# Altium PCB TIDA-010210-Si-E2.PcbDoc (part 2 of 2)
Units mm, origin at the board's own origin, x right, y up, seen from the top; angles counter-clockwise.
Board outline 75 x 60 mm, 2 copper layers (Top Layer, Bottom Layer), stack 1.565 mm thick; 77 components, 33 nets, 164 pads, 32 vias.
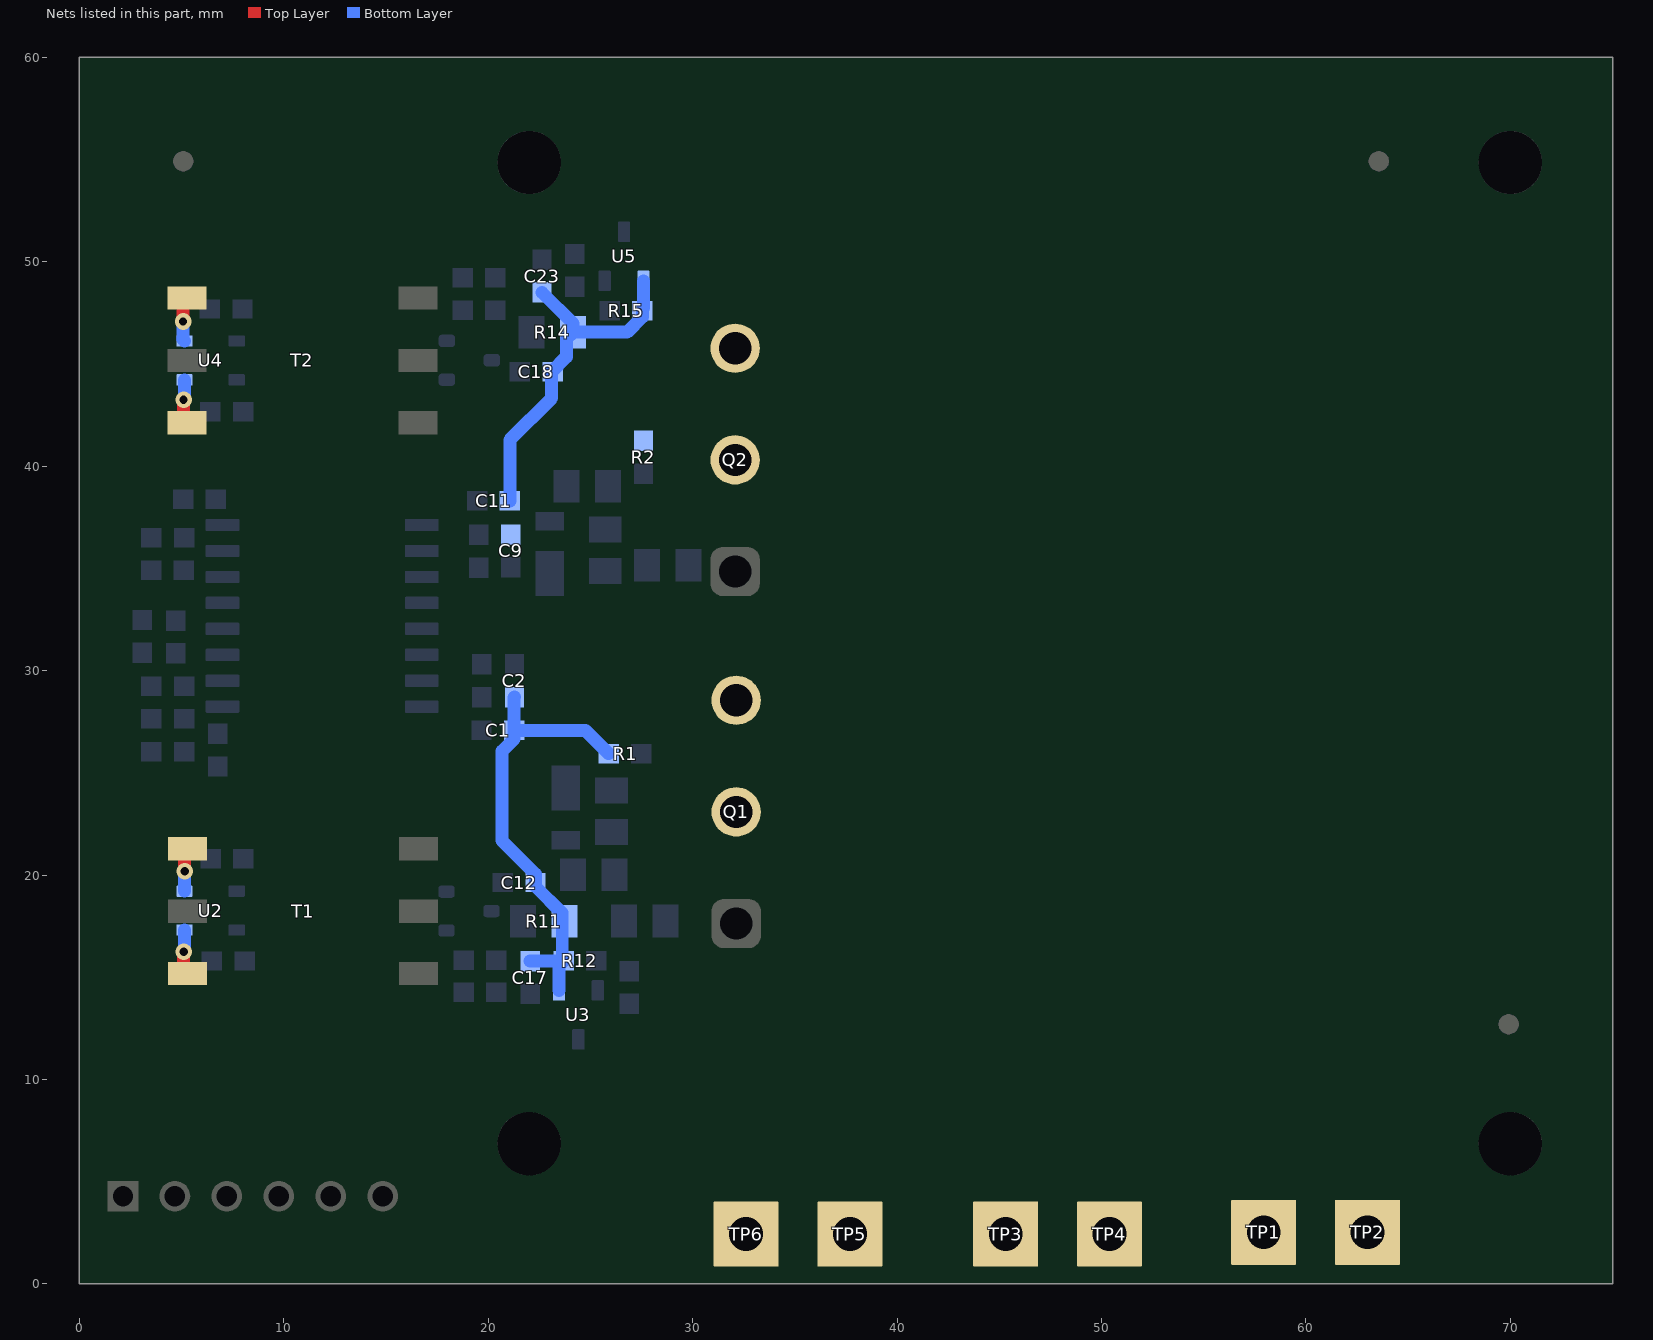
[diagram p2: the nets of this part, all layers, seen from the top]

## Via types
v1: diameter 0.813, hole 0.406, Top Layer to Bottom Layer, tented both sides, 31 vias
v2: diameter 0.813, hole 0.406, Top Layer to Bottom Layer, 1 vias

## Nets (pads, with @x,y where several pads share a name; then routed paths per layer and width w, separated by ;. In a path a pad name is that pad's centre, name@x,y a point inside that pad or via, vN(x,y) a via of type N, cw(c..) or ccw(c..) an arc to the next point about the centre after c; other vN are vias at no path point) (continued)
NetT1_1: T1.1 U2.3 | length 2.1
  Top Layer w0.63: v1(5.149,20.191) 5.149,21.149 T1.1@5.286,21.285
  Bottom Layer w0.635: U2.3@5.144,19.211 5.144,20.186 v1(5.149,20.191)
NetT1_3: T1.3 U2.1 | length 2.2
  Top Layer w0.63: v1(5.099,16.254) 5.099,15.372 T1.3@5.286,15.185
  Bottom Layer w0.635: v1(5.099,16.254) 5.144,16.3 U2.1@5.144,17.311
NetT2_1: T2.1 U4.3 | length 2.2
  Top Layer w0.63: v1(5.072,47.081) 5.072,48.039 T2.1@5.259,48.226
  Bottom Layer w0.635: v1(5.072,47.081) 5.072,46.197 U4.3@5.144,46.126
NetT2_3: T2.3 U4.1 | length 2.2
  Top Layer w0.63: v1(5.098,43.258) 5.098,42.288 T2.3@5.259,42.126
  Bottom Layer w0.635: v1(5.098,43.258) 5.144,43.304 U4.1@5.144,44.226
SW: C1.2 C2.2 C12.2 C17.1 Q1.3 Q2.2 R1.1 R11.1 R12.2 TP1.1 TP2.1 U3.1 | length 22.6
  Bottom Layer w0.635: C2.2@21.284,28.704 21.272,28.692 C1.2@21.272,27.076 ; C17.1@22.047,15.786 R12.2@23.673,15.786 ; U3.1@23.459,14.357 R12.2@23.459,15.471 ; R12.2@23.459,15.573 R12.2@23.673,15.786 ; R1.1@25.895,25.933 24.752,27.076 C1.2@21.272,27.076 ; C1.2@21.272,27.076 21.272,26.657 20.676,26.06 20.676,21.68 22.314,20.042 C12.2@22.314,19.634 22.314,19.444 23.622,18.136 23.622,17.735 23.622,15.862 R12.2@23.686,15.799 R12.2@23.673,15.786
SW+: Q1.2 TP3.1 TP4.1
SW-: C9.2 C11.2 C18.2 C23.1 Q2.3 R2.1 R14.1 R15.2 TP5.1 TP6.1 U5.1 | length 17.6
  Bottom Layer w0.635: C11.2@21.059,38.305 21.059,41.29 23.101,43.332 23.101,44.628 23.825,45.352 23.825,46.228 R14.1@24.155,46.558 ; C23.1@22.631,48.501 24.155,46.977 R14.1@24.155,46.558 ; U5.1@27.595,49.067 27.595,47.74 27.545,47.691 27.545,47.306 26.797,46.558 R14.1@24.155,46.558
pads on no net: "Heat Sink1.1" "Heat Sink1.2" "Heat Sink1.3" "Heat Sink1.4" FID4.1 FID5.1 FID6.1 FID7.1 FID8.1 FID9.1 J1.5 U1.7 U1.12 U1.13

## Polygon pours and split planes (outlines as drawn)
SW- on Top Layer "TOP_LAYER_SW-_P119" (solid, remove dead copper, pour order 119): 50.952,43.926 52.781,42.099 52.781,17.45 41.173,5.842 41.173,2.611 39.223,0.66 29.017,0.66 28.473,1.204 28.473,8.585 35.966,16.078 35.966,42.088 33.96,44.094 31.166,44.094 30.582,44.679 30.582,46.507 31.496,47.422 47.457,47.422
NetD1_1 on Top Layer "TOP_LAYER_NETD1_1_P095" (solid, remove dead copper, pour order 95): 19.619,30.063 22.454,27.229 22.454,23.216 22.123,22.885 20.345,22.885 17.094,26.137 17.094,29.758 17.399,30.063
GND on Top Layer "TOP_LAYER_GND_P067" (solid, remove dead copper, pour order 67): 0.765,38.89 0.765,47.679 2.184,49.098 7.468,49.098 7.496,49.07 7.496,38.489 7.496,12.596 15.151,4.94 15.151,3.632 12.256,0.737 1.626,0.737 0.765,1.597 0.765,25.199
NetD2_1 on Top Layer "TOP_LAYER_NETD2_1_P043" (solid, remove dead copper, pour order 43): 22.276,34.306 22.673,33.909 24.502,33.909 24.816,34.218 24.816,35.792 23.905,36.703 17.399,36.703 17.013,36.317 17.013,35.412 17.155,35.27 18.582,35.27 19.028,34.824 19.028,34.475 19.197,34.306
SW on Bottom Layer "BOTTOM_LAYER_SW_P121" (solid, remove dead copper, pour order 121): 32.925,27.127 52.019,27.127 55.575,23.571 55.575,1.575 56.464,0.686 67.793,0.686 68.631,1.524 68.631,33.68 60.427,41.885 31.394,41.885 30.632,41.123 30.632,39.472 31.369,38.735 33.571,38.735 35.966,36.339 35.966,33.299 33.376,30.709 23.368,30.709 21.996,29.337 20.813,29.337 20.559,29.083 20.559,26.685 20.86,26.384 26.384,26.384 27.11,27.11 32.907,27.11
SW+ on Bottom Layer "BOTTOM_LAYER_SW+_P117" (solid, remove dead copper, pour order 117): 43.424,11.898 33.706,21.615 31.369,21.615 30.709,22.276 30.709,24.105 31.115,24.511 48.692,24.511 52.781,20.422 52.781,1.295 52.121,0.635 43.993,0.635 43.424,1.204
GND on Bottom Layer "BOTTOM_LAYER_GND_P111" (solid, remove dead copper, pour order 111): 7.188,40.963 8.414,42.189 8.414,48.151 7.468,49.098 2.184,49.098 0.765,47.679 0.765,1.597 1.626,0.737 12.256,0.737 15.151,3.632 15.151,4.94 8.441,11.651 8.441,24.63 7.188,25.883
+12Va on Bottom Layer "BOTTOM_LAYER_+12VA_P109" (solid, remove dead copper, pour order 109): 19.355,19.341 19.761,18.935 19.761,13.894 19.888,13.767 20.973,13.767 21.125,13.919 21.125,16.61 21.234,16.719 22.206,16.719 22.377,16.891 22.377,18.52 22.127,18.771 21.641,18.771 21.234,19.177 21.234,20.085 19.793,21.526 19.494,21.526 19.355,21.387
+12Vb on Bottom Layer "BOTTOM_LAYER_+12VB_P107" (solid, remove dead copper, pour order 107): 19.787,44.45 20.091,44.145 22.047,44.145 22.2,44.298 22.2,45.364 22.377,45.542 22.759,45.542 22.962,45.745 22.962,47.193 22.581,47.574 21.92,47.574 21.615,47.879 21.615,49.352 21.26,49.708 19.837,49.708 19.837,49.706 19.685,49.553 19.685,48.285 19.787,48.184
NetD1_2 on Bottom Layer "BOTTOM_LAYER_NETD1_2_P105" (solid, remove dead copper, pour order 105): 23.038,22.377 22.606,21.946 22.606,21.108 23.292,20.422 23.292,19.45 23.743,18.999 24.759,18.999 24.962,19.202 24.962,20.784 24.663,21.082 24.663,22.2 24.486,22.377
NetL1_1 on Bottom Layer "BOTTOM_LAYER_NETL1_1_P103" (solid, remove dead copper, pour order 103): 27.127,16.739 25.639,16.739 25.359,17.018 25.359,20.889 25.014,21.234 25.014,22.638 25.287,22.911 26.645,22.911 26.822,22.733 26.822,21.016 27.381,20.457 27.381,16.993
G1H_P on Bottom Layer "BOTTOM_LAYER_G1H_P_P101" (solid, remove dead copper, pour order 101): 33.004,18.821 33.35,18.475 33.35,16.767 32.995,16.411 28.185,16.411 27.807,16.789 27.807,18.586 28.042,18.821
+12Va on Bottom Layer "BOTTOM_LAYER_+12VA_P099" (solid, remove dead copper, pour order 99): 15.981,28.423 16.106,28.547 18.673,28.547 19.329,29.202 20.15,29.202 20.226,29.126 20.226,26.627 19.964,26.365 17.551,26.365 15.981,27.935
-5Va on Bottom Layer "BOTTOM_LAYER_-5VA_P097" (solid, remove dead copper, pour order 97): 15.981,30.963 15.981,30.967 16.307,31.293 21.71,31.293 21.975,31.028 21.971,31.024 21.971,29.972 21.733,29.734 19.395,29.734 19.395,29.969 18.884,30.48 16.096,30.48 15.981,30.594
NetD1_1 on Bottom Layer "BOTTOM_LAYER_NETD1_1_P089" (solid, remove dead copper, pour order 89): 21.336,25.146 21.336,23.203 21.654,22.885 24.587,22.885 25.095,23.393 26.721,23.393 26.822,23.495 26.822,24.892 26.619,25.095 25.159,25.095 24.651,25.603 21.793,25.603
G1L_P on Bottom Layer "BOTTOM_LAYER_G1L_P_P087" (solid, remove dead copper, pour order 87): 29.616,36.398 29.108,35.89 29.108,33.68 29.515,33.274 32.893,33.274 33.528,33.909 33.528,35.719 32.849,36.398
NetL2_1 on Bottom Layer "BOTTOM_LAYER_NETL2_1_P085" (solid, remove dead copper, pour order 85): 25.221,39.827 25.221,39.824 24.994,39.596 24.994,37.744 24.79,37.541 24.79,36.246 24.917,36.119 26.467,36.119 26.975,35.611 26.975,34.315 27.203,34.087 28.372,34.087 28.626,34.341 28.626,36.792 26.721,38.697 26.721,39.649 26.543,39.827
NetD2_2 on Bottom Layer "BOTTOM_LAYER_NETD2_2_P083" (solid, remove dead copper, pour order 83): 22.327,36.881 22.327,39.116 23.037,39.827 24.46,39.827 24.613,39.675 24.613,37.916 24.384,37.688 24.384,37.008 24.181,36.805 22.402,36.805
+12Vb on Bottom Layer "BOTTOM_LAYER_+12VB_P081" (solid, remove dead copper, pour order 81): 15.981,34.773 15.981,34.404 15.981,34.387 16.307,34.061 21.234,34.061 21.615,34.442 21.615,35.509 21.488,35.636 19.501,35.636 18.739,34.874 16.083,34.874
-5Vb on Bottom Layer "BOTTOM_LAYER_-5VB_P079" (solid, remove dead copper, pour order 79): 15.981,37.313 15.981,38.003 17.196,39.218 19.558,39.218 19.939,38.837 19.939,36.346 19.763,36.17 19.119,36.17 18.484,36.805 16.121,36.805 15.981,36.944
SW- on Bottom Layer "BOTTOM_LAYER_SW-_P077" (solid, remove dead copper, pour order 77): 32.791,44.094 33.61,44.913 33.61,46.578 32.791,47.422 28.829,47.422 27.28,45.872 25.728,45.872 23.661,43.805 21.644,43.805 20.372,42.534 20.377,36.417 20.701,36.093 21.565,36.096 21.906,36.437 21.906,39.331 22.809,40.234 26.619,40.234 30.48,44.094
NetD1_1 on Bottom Layer "BOTTOM_LAYER_NETD1_1_P047" (solid, remove dead copper, pour order 47): 18.569,30.063 18.926,29.706 18.926,29.167 18.776,29.016 15.991,29.017 15.864,29.144 15.864,29.972 15.955,30.063
NetD2_1 on Bottom Layer "BOTTOM_LAYER_NETD2_1_P045" (solid, remove dead copper, pour order 45): 17.721,36.375 18.342,36.375 18.621,36.096 18.621,35.605 18.446,35.43 15.946,35.43 15.889,35.487 15.889,36.215 16.049,36.375
NetD2_1 on Bottom Layer "BOTTOM_LAYER_NETD2_1_P039" (solid, remove dead copper, pour order 39): 22.415,36.218 22.243,36.043 22.243,34.381 22.715,33.909 26.289,33.909 26.542,34.162 26.544,35.483 26.264,35.763 24.486,35.763 24.031,36.218

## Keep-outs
Keep-Out Layer:
  circle w0.254: c22.005,54.858 r3.8
  circle w0.254: c22.005,6.858 r3.8
  circle w0.254: c70.005,6.858 r3.8
  circle w0.254: c70.005,54.858 r3.8
  lines w0.254: 0,0 0,60 75,60 75,0 0,0
  text ".Layer_Name" at -31.579,-41.497 h1.52

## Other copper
Top Layer:
  text ".Layer_Name" at -31.579,-41.497 h1.52
Bottom Layer:
  text ".Layer_Name" at -31.579,-41.497 h1.52

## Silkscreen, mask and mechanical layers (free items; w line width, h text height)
Top Overlay:
  lines w0.2: 17.005,22.86 17.005,40.31
  text "Si MOSFET Half-Bridge" at 40.846,8.889 h0.89
  text "5V" at 10.135,5.537 h1.27 r90
  text "GND" at 15.24,5.486 h1.27 r90
  text "PWM1A" at 2.54,5.461 h1.27 r90
  text "PWM1B" at 5.08,5.461 h1.27 r90
  text "EN/Fault" at 7.722,5.461 h1.27 r90
  text "SW+" at 52.654,0.559 h1.52
  text "SW" at 65.481,0.559 h1.52
  text "SW-" at 27.661,0.533 h1.52
  text ".Layer_Name" at -31.579,-41.497 h1.52
Bottom Overlay:
  circle w0.254: c8.585,26.873 r0.361
  lines w0.152: 8.262,27.553 15.477,27.553 ; 8.262,37.814 15.477,37.814 ; 24.922,51.104 24.922,51.896 25.909,52.883 ; 26.009,16.491 27.603,16.491 28.423,15.672
  text ".PRJ_Number" at 55.118,52.603 h3.05
  text "PWM1A" at 1.727,5.461 h1.27 r270
  text "PWM1B" at 4.267,5.461 h1.27 r270
  text "EN/Fault" at 6.909,5.461 h1.27 r270
  text "5V" at 9.347,5.461 h1.27 r270
  text "GND" at 14.427,5.461 h1.27 r270
  text "SW-" at 36.703,4.902 h1.52
  text "SW+" at 49.378,4.851 h1.52
  text "SW" at 61.493,4.79 h1.52
  text ".Layer_Name" at -31.579,-41.497 h1.52
Top Paste:
  text ".Layer_Name" at -31.579,-41.497 h1.52
Bottom Paste:
  text ".Layer_Name" at -31.579,-41.497 h1.52
Top Solder:
  text ".Layer_Name" at -31.579,-41.497 h1.52
  text ".Layer_Name" at -31.579,-41.497 h1.52
Bottom Solder:
  text ".Layer_Name" at -31.579,-41.497 h1.52
Drill Guide:
  text ".Layer_Name" at -31.579,-41.497 h1.52
M1 Board Outline:
  the board outline again, w0.254
  text ".Layer_Name" at -31.579,-41.497 h1.52
M2 Board Dimensions:
  rectangle: -43.06,-29.851 -33.535,-26.676
  rectangle: -46.235,-26.676 -43.06,-23.501
  lines w0.178: -46.235,-26.676 -20.835,-26.676 ; -43.06,-29.851 -43.06,-23.501 ; -39.885,-29.851 -39.885,-23.501 ; -33.535,-29.851 -33.535,-23.501 ; -27.185,-29.851 -27.185,-23.501 ; -46.235,-29.851 -46.235,-23.501 -20.835,-23.501 -20.835,-29.851 -46.235,-29.851
  text ".Layer_Name" at -31.579,-41.497 h1.52
M3 3D STEP Top:
  text ".Layer_Name" at -31.579,-41.497 h1.52
M4 3D STEP Bottom:
  text ".Layer_Name" at -31.579,-41.497 h1.52
M5 Assembly Top:
  lines w0.254: -53.652,-43.317 113.988,-43.317 ; -53.652,-38.153 114.039,-38.153 ; -53.652,-32.988 -53.652,-48.482 48.075,-48.482 114.039,-48.482 114.039,-32.988 -53.639,-32.988 -53.639,-48.482 -13.621,-48.482 ; 8.959,-48.482 8.959,-32.988 ; 41.141,-38.153 41.141,-32.988 ; 62.477,-38.153 62.477,-32.988 ; 78.276,-48.647 78.276,-43.495
  text "COMPONENTS MARKED 'DNP' SHOULD NOT BE POPULATED." at -16.936,-27.781 h0.46
  text "ASSEMBLY VARIANT:" at -16.949,-30.715 h0.46
  text ".VariantName" at 9.366,-30.715 h0.46
  text "PCB VIEWED FROM TOP SIDE" at -52.039,-36.345 h0.46
  text "BOARD #:" at 10.864,-36.345 h0.46
  text ".PRJ_Number" at 24.72,-36.345 h0.46
  text "REV:" at 46.17,-36.345 h0.46
  text ".PCB_Rev" at 53.574,-36.345 h0.46
  text "SVN REV:" at 67.455,-36.345 h0.46
  text ".VersionControl_RevNumber" at 80.308,-36.345 h0.46
  text ".Layer_Name" at -31.775,-41.482 h0.46
  text "TID #:" at 10.864,-41.51 h0.46
  text ".TID" at 24.72,-41.51 h0.46
  text "LAYER NAME =" at -52.039,-41.548 h0.46
  text "PLOT NAME =" at -52.039,-46.725 h0.46
  text ".plot_File_Name" at -31.579,-46.725 h0.46
  text "GENERATED    :" at 10.915,-46.725 h0.46
  text ".Print_Date" at 33,-46.725 h0.46
  text ".Print_Time" at 51.517,-46.725 h0.46
  text "TEXAS INSTRUMENTS" at 83.635,-46.725 h0.46
M6 Assembly Bottom:
  circle w0.254: c23.47,13.454 r0.254
  circle w0.254: c18.872,17.272 r0.254
  circle w0.254: c6.115,17.321 r0.254
  circle w0.254: c6.088,44.236 r0.254
  circle w0.254: c18.933,44.216 r0.254
  circle w0.254: c27.595,50.089 r0.254
  circle w0.254: c8.585,28.143 r0.254
  lines w0.254: -53.664,-38.165 114.026,-38.165 ; -53.614,-43.33 114.026,-43.33 ; -17.901,-48.66 -17.901,-43.508 ; -2.102,-38.165 -2.102,-33.001 ; 11.532,-38.061 11.532,-32.897 ; 51.415,-48.495 51.415,-33.001 ; 73.996,-48.495 114.014,-48.495 114.014,-33.001 -53.664,-33.001 -53.664,-48.495 12.299,-48.495 114.026,-48.495 114.026,-33.001
  text "COMPONENTS MARKED 'DNP' SHOULD NOT BE POPULATED." at 108.756,-27.768 h0.46
  text ".VariantName" at 82.238,-30.715 h0.46
  text "ASSEMBLY VARIANT:" at 108.629,-30.715 h0.46
  text "Final_Gerber_XTIDA-ANPC-DC2_20200401" at 55.474,-35.636 h1.52
  text "REV:" at 7.823,-36.275 h0.46
  text ".VersionControl_RevNumber" at -19.933,-36.358 h0.46
  text "SVN REV:" at -7.081,-36.358 h0.46
  text "BOARD #:" at 49.51,-36.358 h0.46
  text "PCB VIEWED FROM BOTTOM SIDE" at 112.413,-36.358 h0.46
  text ".PCB_Rev" at 1.499,-36.377 h0.46
  text ".PRJ_Number" at 42.088,-36.656 h0.46
  text ".Layer_Name" at 103.607,-40.898 h0.46
  text "LAYER NAME =" at 112.147,-41.167 h0.46
  text ".TID" at 35.655,-41.522 h0.46
  text "TID #:" at 49.51,-41.522 h0.46
  text "TEXAS INSTRUMENTS" at -23.261,-46.738 h0.46
  text ".Print_Time" at 8.858,-46.738 h0.46
  text ".Print_Date" at 27.374,-46.738 h0.46
  text "GENERATED    :" at 49.46,-46.738 h0.46
  text "PLOT NAME =" at 112.413,-46.738 h0.46
  text ".plot_File_Name" at 100.863,-46.867 h0.46
M9 Title Sheet:
  drawing of 57 lines, arcs and shapes, not listed
  text "1" at -27.443,184.436 h1.78
  text "2" at 35.947,184.436 h1.78
  text "3" at 99.176,184.436 h1.78
  text "4" at 162.845,184.436 h1.78
  text "5" at 226.32,184.436 h1.78
  text "6" at 289.947,184.436 h1.78
  text "A" at -56.814,155.404 h1.78
  text "A" at 319.106,155.404 h1.78
  text "A" at 319.157,155.384 h1.78
  text "B" at -56.814,94.952 h1.78
  text "B" at 319.106,94.952 h1.78
  text "B" at 319.157,94.932 h1.78
  text "C" at -56.814,34.627 h1.78
  text "C" at 319.106,34.627 h1.78
  text "C" at 319.157,34.607 h1.78
  text "PROJECT TITLE:" at 241.89,-12.642 h1.14
  text ".PRJ_Title" at 243.16,-16.029 h1.78
  text "DESIGNED FOR:" at 241.89,-20.288 h1.14
  text ".PRJ_Customer" at 243.16,-23.844 h1.78
  text "D" at -56.814,-25.571 h1.78
  text "D" at 319.106,-25.571 h1.78
  text "FILE NAME:" at 241.89,-27.908 h1.14
  text ".PCB_File_Name_No_Path" at 249.222,-30.787 h1.78
  text "Texas Instruments (TI) and/or its licensors do not warrant the accuracy or completeness of this specification" at 115.665,-35.067 h1.14
  text "ENGINEER:" at 241.89,-35.274 h1.14
  text "LAYOUT BY:" at 280.117,-35.274 h1.14
  text "or any information contained therein. TI and/or its licensors do not warrant that this design will meet" at 114.522,-37.928 h1.14
  text ".PRJ_Engineer" at 243.16,-39.211 h1.78
  text ".PCB_Layout" at 281.4,-39.211 h1.78
  text "the specifications, will be suitable for your application or fit for any particular purpose, or will operate in" at 114.522,-40.79 h1.14
  text "ALTIUM DESIGNER VERSION:" at 280.117,-43.148 h1.14
  text "an implementation. TI and/or its licensors do not warrant that the design is production worthy. You should" at 114.522,-43.652 h1.14
  text "completely validate and test your design implementation to confirm the system functionality for your application." at 115.665,-46.513 h1.14
  text ".print_Scale" at 243.16,-46.534 h1.78
  text ".Application_BuildNumber" at 281.4,-46.534 h1.78
  text "1" at -27.443,-51.784 h1.78
  text "2" at 35.947,-51.784 h1.78
  text "3" at 99.176,-51.784 h1.78
  text "4" at 162.845,-51.784 h1.78
  text "5" at 226.32,-51.784 h1.78
  text "6" at 289.947,-51.784 h1.78
M10 Fab Notes:
  drawing of 227 lines, arcs and shapes, not listed
  text "DESIGN INFORMATION" at 268.001,153.028 h1.52
  text "(REFER ALSO ARRAY/PANEL PROFILING INFORMATION)" at 259.072,148.809 h1.52
  text "BOARD SIZE" at 241.648,148.7 h1.52
  text "75MM" at 254.323,145.872 h1.52
  text "60MM" at 272.593,145.694 h1.52
  text "X" at 266.235,145.454 h1.52
  text "Number of Layers :" at 251.884,140.445 h1.52
  text "2" at 279.126,140.318 h1.52
  text "15" at 279.15,136.971 h1.52
  text "MIN. TRACK WIDTH:" at 251.884,136.915 h1.52
  text "MIL" at 283.659,136.915 h1.52
  text "MIN. CLEARANCE:" at 251.884,133.562 h1.52
  text "MIL" at 283.659,133.562 h1.52
  text "7.87" at 277.284,133.426 h1.52
  text "16" at 278.867,130.425 h1.52
  text "MIN. VIA DRILL SIZE:" at 251.884,130.209 h1.52
  text "MIL" at 283.659,130.209 h1.52
  text "6 MIL ( 0.1524 mm)" at 269.537,126.61 h1.52
  text "MINIMUM ANNULAR RING" at 243.521,126.501 h1.52
  text "EXTERNAL" at 292.182,126.221 h1.52
  text "PER" at 248.601,123.504 h1.52
  text "IPC-D-275 CLASS 2 LEVEL C" at 254.189,123.504 h1.52
  text "+/-" at 282.022,120.633 h1.52
  text "MIL, HOLES" at 291.99,120.652 h1.52
  text "+/-" at 303.714,120.633 h1.52
  text "REGISTRATION TOLERANCES:" at 243.521,120.506 h1.52
  text "METAL" at 273.996,120.506 h1.52
  text "5" at 288.631,120.506 h1.52
  text "3" at 309.789,120.506 h1.52
  text "MIL" at 312.742,120.506 h1.52
  text "MATERIAL:" at 241.622,115.186 h1.52
  text "FR-4 High Tg" at 266.678,111.622 h1.52
  text "X" at 262.642,111.413 h1.52
  text "FR-408" at 252.316,111.404 h1.52
  text "OTHER" at 290.111,111.404 h1.52
  text "63 MIL (1.6mm) +/-10%" at 260.446,107.271 h1.52
  text "THICKNESS:" at 243.521,107.162 h1.52
  text "X" at 257.191,107.162 h1.52
  text "OTHER" at 293.083,107.162 h1.52
  text "TOLERANCE:" at 243.521,103.149 h1.52
  text "X" at 264.84,103.149 h1.52
  text "ANSI IPC-6012 TYPE 3 CLASS 2" at 269.588,103.149 h1.52
  text "OTHER +/-" at 269.588,99.187 h1.52
  text "BOW & TWIST:" at 243.521,95.199 h1.52
  text "X" at 264.84,95.199 h1.52
  text "ANSI IPC-6012 TYPE 3 CLASS 2" at 269.588,95.199 h1.52
  text "OTHER +/-" at 269.588,91.173 h1.52
  text "COPPER THICKNESS (FINISHED):" at 241.622,87.731 h1.52
  text "1.4MIL (1oz)" at 263.974,83.852 h1.52
  text "2MIL (1.4oz)" at 283.456,83.852 h1.52
  text "2.8MIL (2oz)" at 301.922,83.852 h1.52
  text "OUTER:" at 250.69,83.743 h1.52
  text "X" at 298.526,83.693 h1.52
  text "1.4MIL (1oz)" at 263.974,79.864 h1.52
  text "2.8MIL (2oz)" at 283.456,79.864 h1.52
  text "N/A" at 301.91,79.874 h1.52
  text "INNER SIGNAL:" at 243.347,79.756 h1.52
  text "DRILLING:" at 241.622,76.225 h1.52
  text "REFERENCE:" at 243.521,73.253 h1.52
  text "X" at 259.986,73.253 h1.52
  text "AS SHOWN" at 264.736,73.253 h1.52
  text "X" at 282.872,73.253 h1.52
  text "NC_DRILL FILES" at 286.352,73.253 h1.52
  text "PTH MIN COPPER THICKNESS:" at 243.521,69.24 h1.52
  text "X" at 277.817,69.24 h1.52
  text "1MIL" at 281.297,69.24 h1.52
  text "OTHER" at 293.921,69.24 h1.52
  text "BOARD FINISH:" at 241.622,65.201 h1.52
  text "X" at 282.562,62.306 h1.52
  text "SILKSCREEN:" at 245.565,62.204 h1.52
  text "X" at 269.664,62.204 h1.52
  text "TOP" at 272.864,62.204 h1.52
  text "BOTTOM" at 285.844,62.204 h1.52
  text "SILKSCREEN COLOR:" at 245.565,57.962 h1.52
  text "X" at 269.637,57.962 h1.52
  text "WHITE" at 272.864,57.962 h1.52
  text "OTHER" at 285.844,57.962 h1.52
  text "SOLDER RESIST COLOR:" at 245.565,53.644 h1.52
  text "X" at 259.985,49.601 h1.52
  text "GREEN" at 263.212,49.601 h1.52
  text "BLUE" at 278.224,49.601 h1.52
  text "OTHER" at 291.889,49.601 h1.52
  text "IMMERSION GOLD (ENIG)" at 268.572,44.812 h1.52
  text "ENEPIG" at 302.545,44.729 h1.52
  text "SURFACE FINISH:" at 241.622,44.704 h1.52
  text "X" at 263.823,44.704 h1.52
  text "IMM. TIN/SILVER OR EQUIV" at 249.993,40.716 h1.52
  text "OTHER" at 286.352,40.716 h1.52
  text "X" at 263.72,36.296 h1.52
  text "ARRAY/PANEL:" at 241.622,36.169 h1.52
  text "CUT AND TRIM PER MECH LAYER 1" at 268.572,36.06 h1.52
  text "N.C. ROUTE" at 268.572,32.207 h1.52
  text "V. SCORE" at 290.568,32.207 h1.52
  text "CERTIFICATION:" at 241.622,28.727 h1.52
  text "MATERIALS AND WORKMANSHIP FOR ALL PCBS" at 260.037,28.727 h1.52
  text "TO MEET OR EXCEED THE REQUIREMENTS OF:" at 260.037,26.238 h1.52
  text "X" at 250.55,22.771 h1.52
  text "ANSI IPC-A-600F CLASS ->" at 254.081,22.771 h1.52
  text "X" at 295.713,22.771 h1.52
  text "2" at 298.734,22.771 h1.52
  text "1" at 290.733,22.733 h1.52
  text "3" at 307.726,22.733 h1.52
  text "X" at 250.603,18.719 h1.52
  text "UL 94V-0" at 254.081,18.719 h1.52
  text "X" at 271.227,18.719 h1.52
  text "RoHS" at 274.706,18.719 h1.52
  text "OTHER" at 291.074,18.719 h1.52
  text "PER ORDER" at 301.159,18.719 h1.52
  text "VIA TENTING:" at 272.548,15.325 h1.52
  text "X" at 292.169,15.215 h1.52
  text "ADDITIONAL REQUIREMENTS:" at 241.622,15.138 h1.52
  text "YES" at 286.509,15.094 h1.52
  text "NO" at 295.775,14.962 h1.52
  text "MICROSECTION:" at 243.521,12.217 h1.52
  text "YES" at 266.527,12.217 h1.52
  text "IMPEDANCE CONTROL:" at 273.107,12.048 h1.52
  text "YES" at 298.1,12.023 h1.52
  text "X" at 311.867,11.845 h1.52
  text "NO" at 307.637,11.583 h1.52
  text "REQUIRED" at 288.409,8.251 h1.52
  text "BARE BOARD ELEC. TEST:" at 243.521,8.178 h1.52
  text "NONE" at 276.687,8.178 h1.52
  text "X" at 285.183,8.178 h1.52
  text "PER ORDER" at 303.446,8.178 h1.52
  text "MANUFACTURER'S UL:" at 243.521,4.191 h1.52
  text "RAIL" at 273.131,4.082 h1.52
  text "METAL" at 285.623,4.082 h1.52
  text "X" at 295.154,4.073 h1.52
  text "SILK" at 298.62,4.082 h1.52
  text ".Layer_Name" at -31.579,-41.497 h1.52
M11 Gerber Information:
  lines w0.254: -53.652,-43.317 113.988,-43.317 ; -53.652,-38.153 114.039,-38.153 ; -53.652,-32.988 -53.652,-48.482 48.075,-48.482 114.039,-48.482 114.039,-32.988 -53.639,-32.988 -53.639,-48.482 -13.621,-48.482 ; 10.051,-48.482 10.051,-32.988 ; 49.498,-38.153 49.498,-32.988 ; 62.477,-38.153 62.477,-32.988 ; 78.276,-48.647 78.276,-43.495
  text ".PRJ_Number" at 23.52,-36.246 h1.02
  text "ALL ARTWORK VIEWED FROM TOP SIDE" at -52.039,-36.345 h1.52
  text "BOARD #:" at 10.864,-36.345 h1.52
  text "SVN REV:" at 67.455,-36.345 h1.52
  text ".VersionControl_RevNumber" at 80.308,-36.345 h1.52
  text "REV:" at 52.984,-36.707 h1.52
  text ".PCB_Rev" at 59.411,-36.707 h1.52
  text "LAYER NAME =" at -52.039,-41.497 h1.52
  text "TID #:" at 10.864,-41.51 h1.52
  text ".TID" at 24.72,-41.51 h1.52
  text ".plot_File_Name" at -34.366,-46.533 h1.52
  text "PLOT NAME =" at -52.039,-46.725 h1.52
  text "GENERATED    :" at 10.915,-46.725 h1.52
  text ".Print_Date" at 33,-46.725 h1.52
  text ".Print_Time" at 51.517,-46.725 h1.52
  text "TEXAS INSTRUMENTS" at 83.635,-46.725 h1.52
M12 Stackup:
  drawing of 191 lines, arcs and shapes, not listed
  text "Layer" at 113.547,96.444 h1.52
  text "Name" at 123.958,96.444 h1.52
  text "Material" at 147.574,96.444 h1.52
  text "Thickness" at 169.412,96.444 h1.52
  text "Constant" at 185.918,96.444 h1.52
  text "Board Layer Stack" at 200.392,96.444 h1.52
  text "Top Overlay" at 123.958,93.396 h1.52
  text "Top Solder" at 123.958,90.348 h1.52
  text "Solder Resist" at 147.574,90.348 h1.52
  text "0.40mil" at 169.412,90.348 h1.52
  text "3.5" at 185.918,90.348 h1.52
  text "1" at 113.547,87.3 h1.52
  text "Top Layer" at 123.958,87.3 h1.52
  text "2.80mil" at 169.412,87.3 h1.52
  text "Dielectric 1" at 123.958,84.252 h1.52
  text "FR-4 High Tg" at 147.574,84.252 h1.52
  text "56.00mil" at 169.412,84.252 h1.52
  text "4.2" at 185.918,84.252 h1.52
  text "2" at 113.547,81.204 h1.52
  text "Bottom Layer" at 123.958,81.204 h1.52
  text "2.80mil" at 169.412,81.204 h1.52
  text "Bottom Solder" at 123.958,78.156 h1.52
  text "Solder Resist" at 147.574,78.156 h1.52
  text "0.40mil" at 169.412,78.156 h1.52
  text "3.5" at 185.918,78.156 h1.52
  text "Bottom Overlay" at 123.958,75.108 h1.52
  text ".Layer_Name" at -31.579,-41.497 h1.52
M13 Component Bodies Top:
  text ".Layer_Name" at -31.579,-41.497 h1.52
M14 Component Bodies Bottom:
  text ".Layer_Name" at -31.579,-41.497 h1.52
M15 Courtyards Top:
  text ".Layer_Name" at -31.579,-41.497 h1.52
M16 Courtyards Bottom:
  text ".Layer_Name" at -31.579,-41.497 h1.52
Drill Drawing:
  circle w0.254: c113.831,54.218 r0.7
  lines w0.254: 113.131,44.067 114.531,44.067 114.531,45.467 113.131,45.467 113.131,44.067 ; 113.131,47.567 113.481,47.567 113.831,47.217 114.181,47.567 114.531,47.567 114.181,47.917 114.531,48.267 114.181,48.267 113.831,48.617 113.481,48.267 113.131,48.267 113.481,47.917 113.131,47.567 ; 113.131,51.068 113.831,50.367 114.531,51.068 113.831,51.768 113.131,51.068 ; 113.131,57.018 113.481,57.018 113.481,56.668 114.181,56.668 114.181,57.018 114.531,57.018 114.531,57.718 114.181,57.718 114.181,58.068 113.481,58.068 113.481,57.718 113.131,57.718 113.131,57.018
  lines w0.305: 111.862,43.122 193.822,43.122 ; 111.862,58.873 193.822,58.873 ; 120.431,39.972 120.431,62.023 ; 128.856,39.972 128.856,62.023 ; 145.006,39.972 145.006,62.023 ; 151.58,39.972 151.58,62.023 ; 161.098,39.972 161.098,62.023 ; 179.451,39.972 179.451,62.023 ; 111.862,39.972 193.822,39.972 193.822,62.023 111.862,62.023 111.862,39.972
  text "Symbol" at 113.752,59.818 h1.83
  text "Quantity" at 121.376,59.818 h1.83
  text "Finished Hole Size" at 129.801,59.818 h1.83
  text "Plated" at 145.951,59.818 h1.83
  text "Hole Type" at 152.525,59.818 h1.83
  text "Drill Layer Pair" at 162.043,59.818 h1.83
  text "Hole Tolerance" at 180.396,59.818 h1.83
  text "32" at 121.376,56.668 h1.52
  text "16.00mil (0.406mm)" at 129.801,56.668 h1.52
  text "PTH" at 145.951,56.668 h1.52
  text "Round" at 152.525,56.668 h1.52
  text "Top Layer - Bottom Layer" at 162.043,56.668 h1.52
  text "6" at 121.376,53.518 h1.52
  text "39.37mil (1.000mm)" at 129.801,53.518 h1.52
  text "PTH" at 145.951,53.518 h1.52
  text "Round" at 152.525,53.518 h1.52
  text "Top Layer - Bottom Layer" at 162.043,53.518 h1.52
  text "6" at 121.376,50.367 h1.52
  text "62.00mil (1.575mm)" at 129.801,50.367 h1.52
  text "PTH" at 145.951,50.367 h1.52
  text "Round" at 152.525,50.367 h1.52
  text "Top Layer - Bottom Layer" at 162.043,50.367 h1.52
  text "6" at 121.376,47.217 h1.52
  text "64.96mil (1.650mm)" at 129.801,47.217 h1.52
  text "PTH" at 145.951,47.217 h1.52
  text "Round" at 152.525,47.217 h1.52
  text "Top Layer - Bottom Layer" at 162.043,47.217 h1.52
  text "4" at 121.376,44.067 h1.52
  text "122.05mil (3.100mm)" at 129.801,44.067 h1.52
  text "NPTH" at 145.951,44.067 h1.52
  text "Round" at 152.525,44.067 h1.52
  text "Top Layer - Bottom Layer" at 162.043,44.067 h1.52
  text "54 Total" at 121.376,40.917 h1.52
  text ".Layer_Name" at -31.579,-41.497 h1.52
Mechanical 17:
  text ".Layer_Name" at -31.579,-41.497 h1.52
Mechanical 18:
  text ".Layer_Name" at -31.579,-41.497 h1.52
Mechanical 19:
  text ".Layer_Name" at -31.579,-41.497 h1.52

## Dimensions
75,0 to 75,60 on M2 Board Dimensions
0,0 to 75,0 on M2 Board Dimensions
-46.235,-29.851 to -20.835,-29.851 on M2 Board Dimensions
